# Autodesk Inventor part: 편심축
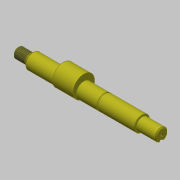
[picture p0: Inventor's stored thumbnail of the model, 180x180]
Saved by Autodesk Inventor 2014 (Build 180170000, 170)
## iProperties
Created: 2016-08
Part Number: 편심축
Material: 강철, 탄소
Document SubType Name: Modeling
Designer: mduedu
Density: 7.87 g/cm^3
Appearance: 밝은 황색
Author: mduedu
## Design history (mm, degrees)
sketch "스케치1"
  geometry: L1 (-70, 0)-(70, 0); L2 (-70, 0)-(-70, 5); L3 (-70, 5)-(-56, 5); L4 (-56, 5)-(-56, 7.5); L5 (-56, 7.5)-(51, 7.5); L6 (51, 7.5)-(51, 6); L7 (51, 6)-(70, 6); L8 (70, 6)-(70, 0); 2 further points
  constraints: 16 end point, 5 parallel, 2 perpendicular, 1 coincident, 1 horizontal, 1 midpoint
  dimensions: "d0" = 140 distance of L1.start L1.end; "d2" = 14 distance of L2.end L3.end; "d3" = 19 distance of L6.end L7.end; "d4" = 10 diameter of L3 L1; "d5" = 15 diameter of L5 L1; "d6" = 12 diameter of L7 L1
revolve "회전1" sketch "스케치1" stored, may be unused: angle "d7" = 90 deg
sketch "스케치2"
  geometry: L1 (-56, -5)-(-56, 5) reference; L2 (70, -6)-(70, 6) reference; L3 (-56, 0)-(70, 0); L4 (-58, 4.5)-(-58, 5); L5 (-58, 5)-(-56, 5); L6 (-56, 5)-(-56, 4.5); L7 (-58, 4.5)-(-56, 4.5); 1 further point
  constraints: 10 end point, 2 midpoint, 1 parallel, 1 perpendicular, 1 point on line
  dimensions: "d8" = 2 distance of L4.end L5.end; "d10" = 10 diameter of L5 L3; "d11" = 9 diameter of L7 L3
revolve "회전2" sketch "스케치2" stored, may be unused: angle "d12" = 90 deg
node "작업 평면1"
sketch "스케치3"
  geometry: C1 r 10.5 at (0, 3); C2 r 7.5 at (0, 0) reference; 1 further point
  constraints: 1 centre point, 1 tangent, 1 vertical alignment
  dimensions: "d14" = 3 distance of C1.centre point (0, 0); "d15" = 21 diameter of C1 (derived)
extrude "돌출1" join sketch "스케치3" distance "d16" = 20; taper "d17" = 0 deg
sketch "스케치5"
  geometry: L1 (-70, -5)-(-70, 5) reference; L2 (70, -6)-(70, 6) reference; L3 (-70, 0)-(70, 0); L4 (-6, 7.5)-(51, 7.5) reference; L5 (15.15, 7.5)-(14, 7.5); L6 (14, 7.5)-(14, 7.15); L7 (14, 7.15)-(15.15, 7.15); L8 (15.15, 7.15)-(15.15, 7.5); 1 further point
  constraints: 10 end point, 2 midpoint, 2 parallel, 1 horizontal, 1 perpendicular, 1 point on line
  dimensions: "d19" = 56 distance between parallel lines of L6 L2; "d20" = 1.15 distance between parallel lines of L8 L6; "d21" = 14.3 diameter of L7 L3
revolve "회전3" sketch "스케치5" stored, may be unused: angle "d22" = 90 deg
node "작업 평면3"
sketch "스케치6"
  geometry: L1 (9.5, 7.5)-(9.5, -7.5) reference; L2 (7.5, 2)-(-9.5, 2); L3 (-9.5, 2)-(-9.5, -2); L4 (-9.5, -2)-(7.5, -2); L5 (-9.5, 6)-(-9.5, -6) reference; A1 r 2 centre (7.5, 0) between (7.5, -2) and (7.5, 2); 2 further points
  constraints: 6 end point, 3 tangent, 2 midpoint, 2 point on circle, 1 centre point, 1 horizontal, 1 horizontal alignment, 1 parallel, 1 perpendicular
  dimensions: "d23" = 4 distance between parallel lines of L4 L2
extrude "돌출2" cut sketch "스케치6" distance "d25" = 2.5; taper "d26" = 0 deg
feature "스레드1" dims "d27" = 10, "d28" = 0
chamfer "모따기5" distance "d41" = 0.5; stored, may be unused: second distance "d42" = 2, angle "d43" = 45 deg
chamfer "모따기6" distance "d44" = 0.5; stored, may be unused: second distance "d45" = 2, angle "d46" = 45 deg
chamfer "모따기7" distance "d47" = 1; stored, may be unused: second distance "d48" = 2, angle "d49" = 45 deg
chamfer "모따기8" distance "d50" = 1; stored, may be unused: second distance "d51" = 2, angle "d52" = 45 deg
sketch "스케치8"
  geometry: 1 further point
hole "구멍1" sketch "스케치8" at (2, 3.5) diameter "d53" = 3.242; stored, may be unused: countersink angle "d57" = 90 deg, drill point angle "d59" = 120 deg; dims "d54" = 10, "d55" = 4, "d56" = 2, "d58" = 12
node "솔리드1"
other parameters: "d13" = -44
